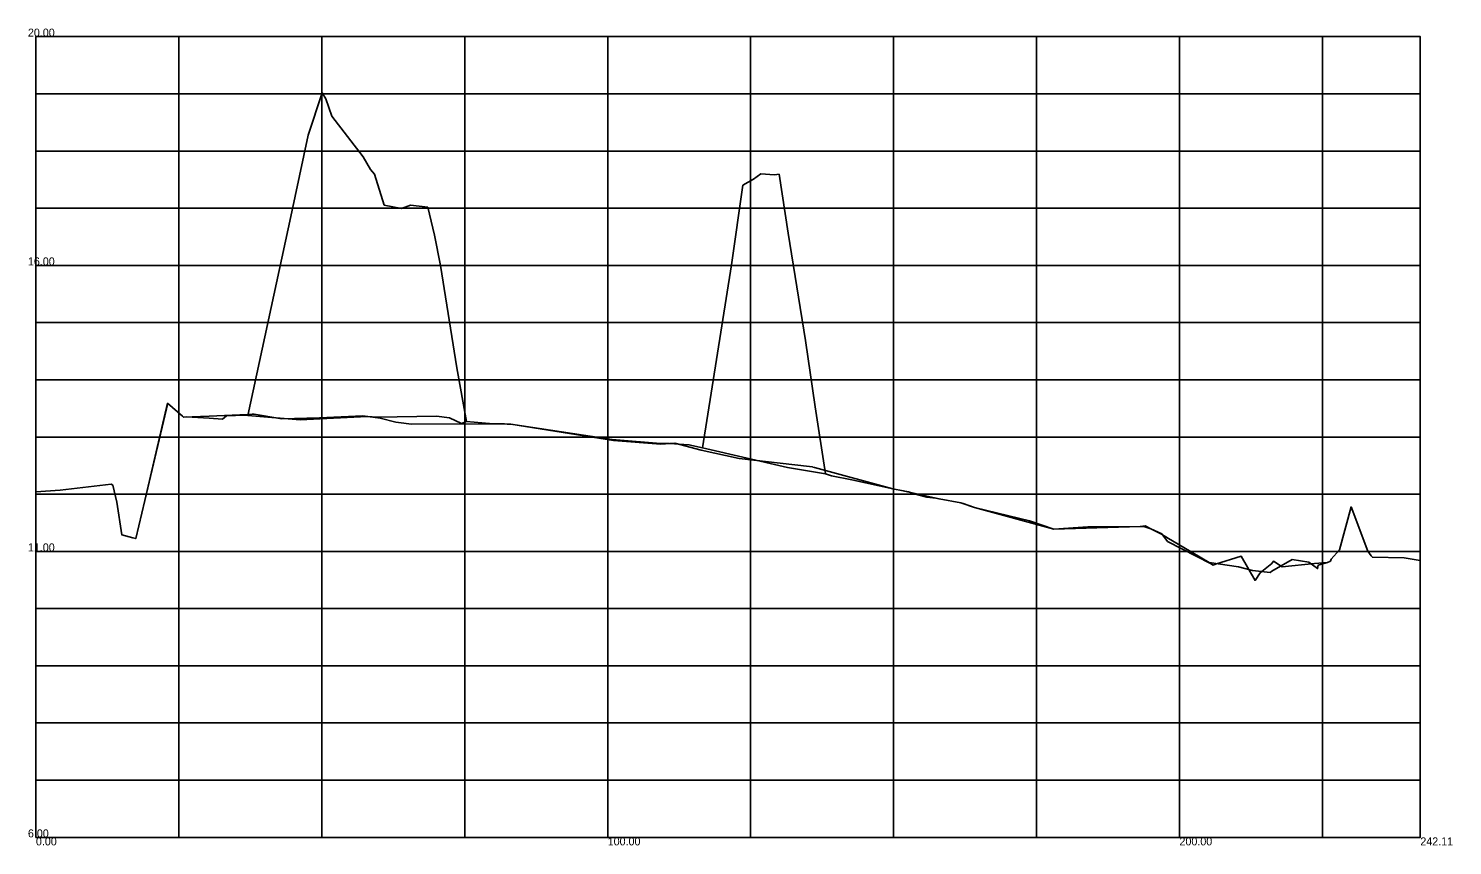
# Model space of a CAD drawing. Extents: x -1 to 1152, y 59 to 201.
# Drawn here: x 561.4 to 810.5, y 58.6 to 201.4 of the extents above; entities that cross this region are included whole.
import ezdxf

# ---------------------------------------------------------------- set-up
doc = ezdxf.new("R2010")
doc.units = 0
doc.layers.add('MAAMUDEL', color=7, linetype='Continuous')

msp = doc.modelspace()

# ---------------------------------------------------------------- linework, layer by layer
at = {"layer": 'MAAMUDEL'}
for p, q in [((587.75, 60), (587.75, 200)), ((612.75, 60), (612.75, 200)), ((637.75, 60), (637.75, 200)), ((662.75, 60), (662.75, 200)), ((687.75, 60), (687.75, 200)), ((712.75, 60), (712.75, 200)), ((737.75, 60), (737.75, 200)), ((762.75, 60), (762.75, 200)), ((787.75, 60), (787.75, 200)), ((562.75, 190), (804.87, 190)), ((562.75, 180), (804.87, 180)), ((562.75, 170), (804.87, 170)), ((562.75, 160), (804.87, 160)), ((562.75, 150), (804.87, 150)), ((562.75, 140), (804.87, 140)), ((562.75, 130), (804.87, 130)), ((562.75, 120), (804.87, 120)), ((562.75, 110), (804.87, 110)), ((562.75, 100), (804.87, 100)), ((562.75, 90), (804.87, 90)), ((562.75, 80), (804.87, 80)), ((562.75, 70), (804.87, 70))]:
    msp.add_line(p, q, dxfattribs=at)
msp.add_lwpolyline([(562.75, 60), (562.75, 200), (804.87, 200), (804.87, 60)], close=True, dxfattribs=at)
for points in [[(562.75, 120.42), (567, 120.72), (575.92, 121.78), (576.19, 121.6), (576.87, 118.59), (577.78, 112.87), (579.69, 112.37), (580.21, 112.25), (581.8, 118.92), (585.82, 135.89), (588.41, 133.63), (588.54, 133.46), (589.08, 133.51), (593.07, 133.27), (595.35, 133.12), (596.09, 133.68), (599.22, 133.8), (599.83, 133.77), (607.31, 168.53), (610.37, 182.79), (612.81, 190.2), (613.46, 189.12), (614.48, 186.11), (619.99, 179), (621.28, 176.79), (621.99, 175.98), (623.68, 170.55), (626.7, 169.94), (628.24, 170.51), (631.27, 170.16), (632.46, 165.3), (633.49, 160.01), (636.34, 142.07), (638.08, 132.71), (642.09, 132.37), (644.68, 132.28), (645.19, 132.27), (645.81, 132.22), (663.54, 129.56), (671.98, 128.85), (673.56, 128.84), (676.96, 128.65), (679.34, 128.1), (684.37, 160.1), (686.41, 174.01), (688.26, 175.08), (689.51, 176), (691.93, 175.83), (692.71, 175.94), (694.29, 165.63), (697.32, 146.87), (699.06, 135.29), (700.84, 123.55), (701.89, 123.23), (705.42, 122.53), (712.62, 120.94), (714.43, 120.59), (715.34, 120.39), (717, 119.9), (718.57, 119.5), (720.13, 119.32), (720.71, 119.19), (724.48, 118.49), (724.94, 118.36), (726.92, 117.67), (740.77, 113.87), (746.73, 114.32), (755.89, 114.35), (756.77, 114.47), (757.74, 113.96), (759.63, 113.02), (760.83, 112.25), (763.48, 110.69), (767.94, 108.06), (773.06, 107.29), (775.52, 106.67), (778.6, 106.3), (778.88, 106.52), (782.44, 108.6), (785.37, 108.13), (786.89, 107.01), (787.02, 107.6), (788.62, 108.03), (789.18, 108.32), (789.27, 108.64), (790.72, 110.25), (792.75, 117.77), (795.71, 110.03), (796.29, 109.2), (796.5, 108.99), (802.02, 108.88), (804.87, 108.41)], [(562.75, 120.42), (567, 120.72), (575.92, 121.78), (576.19, 121.6), (576.87, 118.59), (577.78, 112.87), (579.69, 112.37), (580.21, 112.25), (581.8, 118.92), (585.78, 135.89), (588.41, 133.63), (588.54, 133.46), (593.07, 133.64), (599.73, 133.93), (600.19, 133.93), (600.55, 133.97), (600.92, 133.99), (605.73, 133.18), (612.33, 133.38), (619.9, 133.71), (622.98, 133.31), (625.69, 132.6), (627.12, 132.42), (628.4, 132.24), (641.89, 132.28), (644.68, 132.28), (645.81, 132.22), (663.75, 129.36), (672.04, 128.77), (674.48, 128.92), (679.08, 127.71), (685.75, 126.22), (698.06, 124.84), (698.56, 124.78), (698.64, 124.75), (698.94, 124.67), (712.62, 120.94), (714.43, 120.57), (719.1, 119.52), (720.71, 119.18), (724.48, 118.49), (726.92, 117.67), (736.54, 115.32), (740.77, 113.87), (755.89, 114.35), (756.52, 114.38), (757.74, 113.96), (759.66, 113.05), (760.66, 111.71), (768.17, 107.87), (768.63, 107.61), (769.04, 107.78), (773.56, 109.15), (775.98, 104.93), (776.88, 106.24), (778.88, 107.9), (779.17, 108.27), (780.71, 107.29), (786.38, 107.88), (788.62, 108.03), (789.18, 108.32), (789.27, 108.64), (790.72, 110.25), (792.75, 117.77), (795.71, 110.03), (796.29, 109.2), (796.51, 108.99), (802.02, 108.88), (804.87, 108.41)], [(562.75, 120.42), (567, 120.72), (575.92, 121.78), (576.19, 121.6), (576.87, 118.59), (577.78, 112.87), (579.69, 112.37), (580.21, 112.25), (581.8, 118.92), (585.82, 135.89), (588.41, 133.63), (588.54, 133.46), (589.08, 133.51), (593.07, 133.27), (595.35, 133.12), (596.09, 133.68), (599.22, 133.8), (599.83, 133.77), (608.95, 132.98), (620.66, 133.6), (622.47, 133.48), (632.83, 133.66), (635.07, 133.36), (637.2, 132.35), (638.08, 132.71), (642.09, 132.37), (644.68, 132.28), (645.19, 132.27), (645.81, 132.22), (663.54, 129.56), (671.98, 128.85), (673.56, 128.84), (676.96, 128.65), (679.34, 128.1), (694.21, 124.66), (700.84, 123.55), (701.89, 123.23), (705.42, 122.53), (712.62, 120.94), (714.43, 120.59), (715.34, 120.39), (717, 119.9), (718.57, 119.5), (720.13, 119.32), (720.71, 119.19), (724.48, 118.49), (724.94, 118.36), (726.92, 117.67), (740.77, 113.87), (746.73, 114.32), (755.89, 114.35), (756.77, 114.47), (757.74, 113.96), (759.63, 113.02), (760.83, 112.25), (763.48, 110.69), (767.94, 108.06), (773.06, 107.29), (775.52, 106.67), (778.6, 106.3), (778.88, 106.52), (782.44, 108.6), (785.37, 108.13), (786.89, 107.01), (787.02, 107.6), (788.62, 108.03), (789.18, 108.32), (789.27, 108.64), (790.72, 110.25), (792.75, 117.77), (795.71, 110.03), (796.29, 109.2), (796.5, 108.99), (802.02, 108.88), (804.87, 108.41)]]:
    msp.add_lwpolyline(points, dxfattribs=at)

# ---------------------------------------------------------------- texts
for s, p in [('20.00', (561.35, 200)), ('16.00', (561.35, 160)), ('11.00', (561.35, 110)), ('6.00', (561.35, 60)), ('0.00', (562.75, 58.6)), ('100.00', (662.75, 58.6)), ('200.00', (762.75, 58.6)), ('242.11', (804.87, 58.6))]:
    msp.add_text(s, height=1.4, dxfattribs=at).set_placement(p)

doc.saveas('drawing.dxf')
